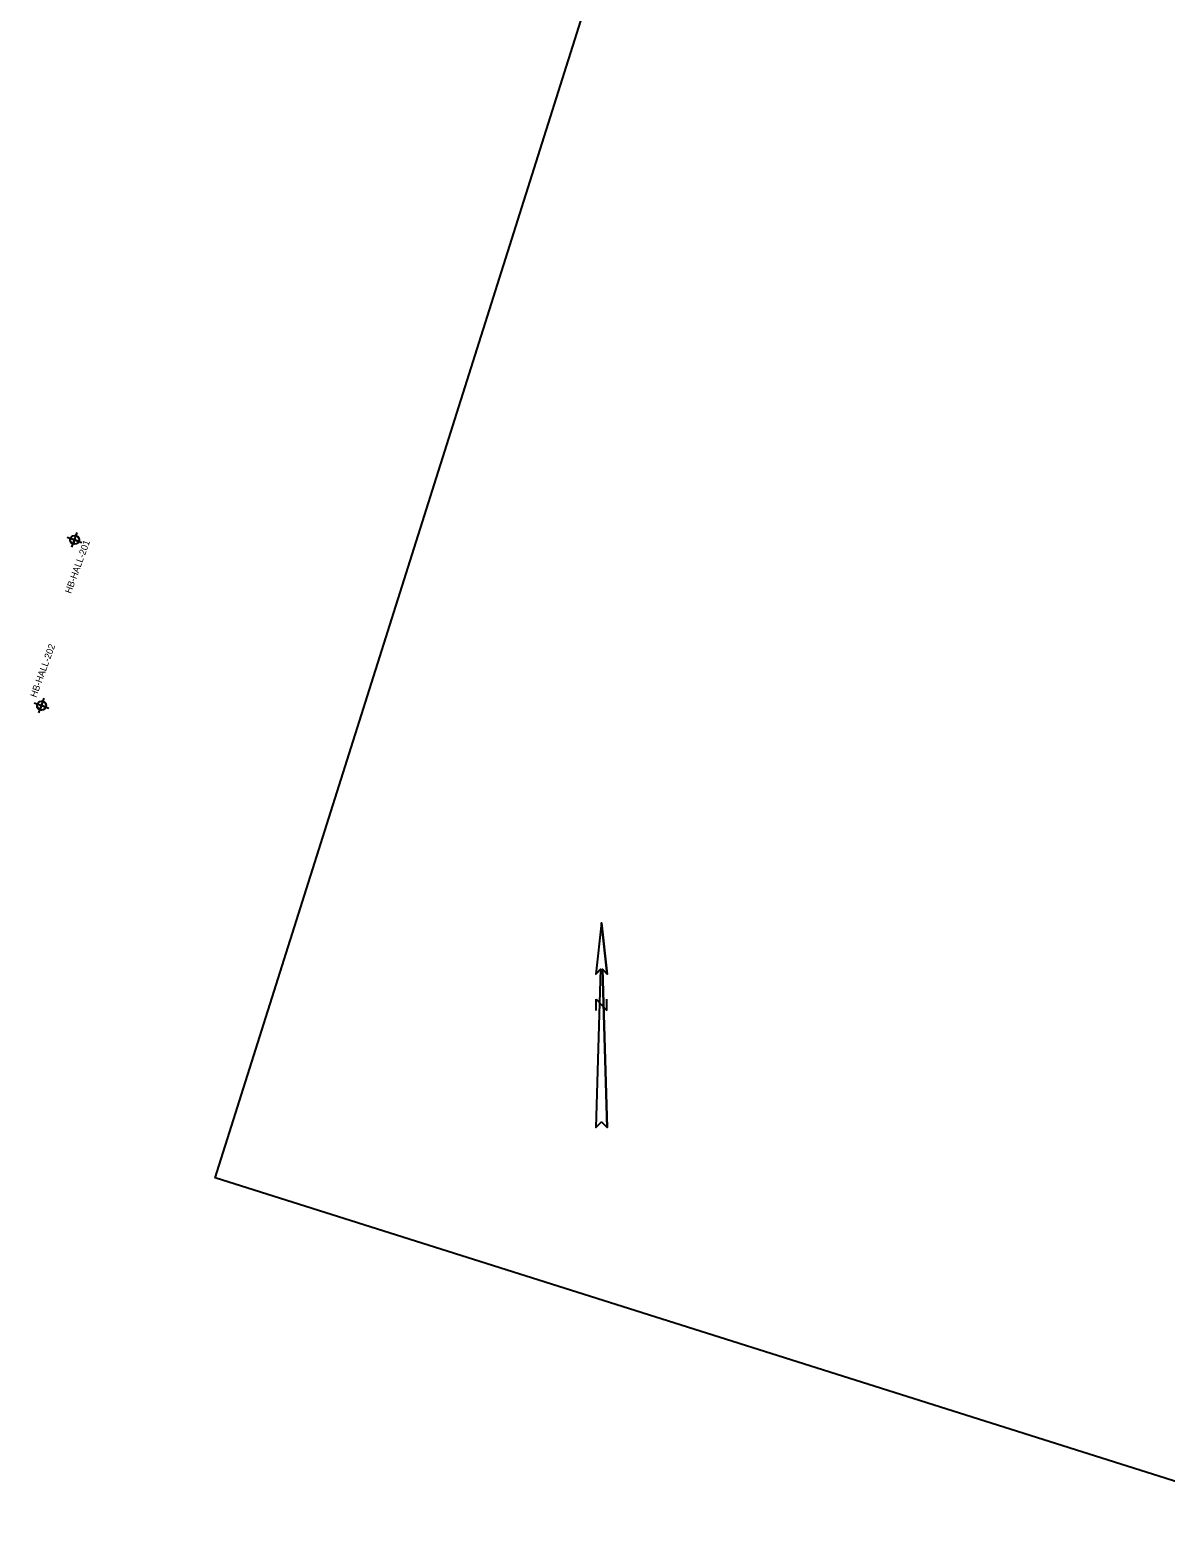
# Model space of a CAD drawing. Extents: x 1136334 to 1137758, y 528745 to 531454.
# Drawn here: x 1136334 to 1136833, y 528960 to 529623 of the extents above; entities that cross this region are included whole.
import ezdxf

# ---------------------------------------------------------------- set-up
doc = ezdxf.new("R2010")
doc.units = 0
for name, color, linetype in [('H_V CONTROLS', 7, 'Continuous'), ('PLOT BOUNDARY', 7, 'Continuous'), ('ROCKS', 7, 'Continuous')]:
    doc.layers.add(name, color=color, linetype=linetype)

msp = doc.modelspace()

# ---------------------------------------------------------------- linework, layer by layer
at = {"layer": 'H_V CONTROLS'}
for p, q in [((1136585.27, 529230.78), (1136582.77, 529208.28)), ((1136585.27, 529230.78), (1136587.77, 529208.28)), ((1136584.88, 529210.4), (1136582.77, 529208.28)), ((1136584.88, 529210.4), (1136582.77, 529140.78)), ((1136585.66, 529210.4), (1136587.77, 529208.28)), ((1136585.66, 529210.4), (1136587.77, 529140.78)), ((1136585.27, 529143.28), (1136582.77, 529140.78)), ((1136585.27, 529143.28), (1136587.77, 529140.78))]:
    msp.add_line(p, q, dxfattribs=at)
for points in [[(1136585.27, 529143.28), (1136587.77, 529140.78), (1136585.66, 529210.4), (1136587.77, 529208.28), (1136585.27, 529230.78), (1136582.77, 529208.28), (1136584.88, 529210.4), (1136582.77, 529140.78), (1136585.27, 529143.28)], [(1136582.91, 529192.28), (1136582.91, 529197.28)], [(1136582.91, 529197.28), (1136587.63, 529192.28)], [(1136587.63, 529192.28), (1136587.63, 529197.28)]]:
    msp.add_lwpolyline(points, dxfattribs=at)
at = {"layer": 'PLOT BOUNDARY'}
msp.add_lwpolyline([(1137142.07, 529675.56), (1136916.06, 528960.42), (1136415.46, 529118.63), (1136641.47, 529833.77)], close=True, dxfattribs=at)
at = {"layer": 'ROCKS'}
for p, q in [((1136350.37, 529400.33), (1136356.84, 529397.97)), ((1136352.42, 529395.92), (1136354.79, 529402.38)), ((1136335.81, 529327.49), (1136342.28, 529325.13)), ((1136337.86, 529323.08), (1136340.23, 529329.54))]:
    msp.add_line(p, q, dxfattribs=at)
for points in [[(1136353.61, 529399.15), (1136352.93, 529397.3), (1136352.68, 529397.42), (1136352.45, 529397.56), (1136352.24, 529397.74), (1136352.03, 529397.97), (1136351.89, 529398.18), (1136351.74, 529398.52), (1136351.68, 529398.74), (1136351.64, 529399.19), (1136351.68, 529399.54), (1136351.76, 529399.83)], [(1136353.61, 529399.15), (1136354.28, 529401), (1136354.53, 529400.88), (1136354.77, 529400.74), (1136354.98, 529400.56), (1136355.18, 529400.33), (1136355.32, 529400.12), (1136355.47, 529399.79), (1136355.53, 529399.56), (1136355.57, 529399.11), (1136355.53, 529398.76), (1136355.45, 529398.47)], [(1136339.05, 529326.31), (1136338.37, 529324.46), (1136338.12, 529324.58), (1136337.89, 529324.72), (1136337.68, 529324.9), (1136337.47, 529325.13), (1136337.33, 529325.34), (1136337.18, 529325.67), (1136337.12, 529325.9), (1136337.08, 529326.35), (1136337.12, 529326.7), (1136337.2, 529326.99)], [(1136339.05, 529326.31), (1136339.72, 529328.16), (1136339.97, 529328.04), (1136340.21, 529327.9), (1136340.42, 529327.72), (1136340.63, 529327.49), (1136340.76, 529327.28), (1136340.91, 529326.94), (1136340.97, 529326.72), (1136341.02, 529326.27), (1136340.97, 529325.92), (1136340.9, 529325.63)]]:
    msp.add_lwpolyline(points, close=True, dxfattribs=at)
for centre in [(1136353.61, 529399.15), (1136339.05, 529326.31)]:
    msp.add_circle(centre, 1.97, dxfattribs=at)

# ---------------------------------------------------------------- texts
for s, p in [('HB-HALL-201', (1136351.98, 529375.31)), ('HB-HALL-202', (1136336.71, 529329.63))]:
    msp.add_text(s, height=2.9528, rotation=69.90541, dxfattribs=at).set_placement(p)

doc.saveas('drawing.dxf')
